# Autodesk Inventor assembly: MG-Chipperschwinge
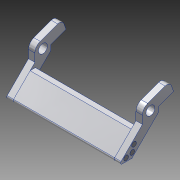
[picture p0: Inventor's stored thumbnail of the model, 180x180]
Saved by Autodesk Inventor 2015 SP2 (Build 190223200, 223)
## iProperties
Created: 2015-08
Part Number: MG-Chipperschwinge
Document SubType Name: Assembly
Designer: rYan
Author: rYan
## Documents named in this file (4)
- E:\Tigers SVN\mechanik\2016\Inventor\Kicker\Chip\MG-Chipperschwinge.iam
- E:\Tigers SVN\mechanik\2016\Inventor\Kicker\Chip\Schwinge Mitte.ipt
- E:\Tigers SVN\mechanik\2016\Inventor\Kicker\Chip\Schwinge Seite.ipt
- E:\Tigers SVN\mechanik\2016\Inventor\Inhaltscenter\de-DE\ISO 2338(1)\ISO 2338 - 3 m6 x 12DIN EN.ipt
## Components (9 placed, 3 different names)
1. Schwinge Mitte:1 — Passend:2, Passend:3, Einfügen:1, Einfügen:2, Einfügen:3, Einfügen:4
2. Schwinge Seite:1 — Einfügen:2, Einfügen:4, Einfügen:8, Einfügen:9, Einfügen:10
3. Schwinge Seite:2 — Einfügen:1, Einfügen:3, Einfügen:5, Einfügen:6, Einfügen:7
4. DIN EN ISO 2338 3 m6 x 12:1 — Einfügen:7
5. DIN EN ISO 2338 3 m6 x 12:2 — Einfügen:6
6. DIN EN ISO 2338 3 m6 x 12:3 — Einfügen:5
7. DIN EN ISO 2338 3 m6 x 12:4 — Einfügen:8
8. DIN EN ISO 2338 3 m6 x 12:5 — Einfügen:9
9. DIN EN ISO 2338 3 m6 x 12:6 — Einfügen:10
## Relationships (12: Insert 10, Mate 2)
- Passend:2 [Mate]: Schwinge Mitte:1
- Passend:3 [Mate]: Schwinge Mitte:1
- Einfügen:1 [Insert]: Schwinge Mitte:1 ↔ Schwinge Seite:2
- Einfügen:2 [Insert]: Schwinge Mitte:1 ↔ Schwinge Seite:1
- Einfügen:3 [Insert]: Schwinge Mitte:1 ↔ Schwinge Seite:2
- Einfügen:4 [Insert]: Schwinge Mitte:1 ↔ Schwinge Seite:1
- Einfügen:5 [Insert]: Schwinge Seite:2 ↔ DIN EN ISO 2338 3 m6 x 12:3
- Einfügen:6 [Insert]: Schwinge Seite:2 ↔ DIN EN ISO 2338 3 m6 x 12:2
- Einfügen:7 [Insert]: Schwinge Seite:2 ↔ DIN EN ISO 2338 3 m6 x 12:1
- Einfügen:8 [Insert]: Schwinge Seite:1 ↔ DIN EN ISO 2338 3 m6 x 12:4
- Einfügen:9 [Insert]: Schwinge Seite:1 ↔ DIN EN ISO 2338 3 m6 x 12:5
- Einfügen:10 [Insert]: Schwinge Seite:1 ↔ DIN EN ISO 2338 3 m6 x 12:6
